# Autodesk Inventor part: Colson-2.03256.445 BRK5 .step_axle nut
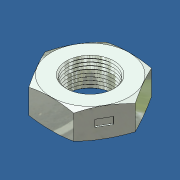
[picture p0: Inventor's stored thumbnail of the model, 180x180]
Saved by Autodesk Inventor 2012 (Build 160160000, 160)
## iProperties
Created: 2010-10
Part Number: Colson-2.03256.445 BRK5 .step_axle nut
Document SubType Name: Modeling
Designer: Administrator
Density: 7.85 g/cm^3
Material: Steel
Mass: 4.83938 g
Surface Area: 6.79431 cm^2
Volume: 0.616482 cm^3
Author: Administrator
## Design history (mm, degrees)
feature "Base1"
body "Solid1"
